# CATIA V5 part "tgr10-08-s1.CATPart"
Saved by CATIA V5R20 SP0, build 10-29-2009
Part number: TGR10-08-S1
Revision: 3
Definition: design
Nomenclature: TGR10-08-S1
Source: made
Description: NOT SPECIFIED
Bounding box of the stored display mesh (mm): x -22 to 0.8, y 0 to 10, z -5 to 5
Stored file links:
  C:\Users\Raffaele\Desktop\3D X SITO CF\I-MOLD\TGR-S1\tgr10-s1.step\tgr10-08-s1.CATPart
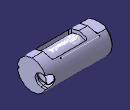
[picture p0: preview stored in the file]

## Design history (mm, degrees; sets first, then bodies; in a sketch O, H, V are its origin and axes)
Set1
  Line1 "LINE #4362": stored without definition
  DatumCurve1 "COMPOSITE_CURVE #4422"
  DatumCurve2 "COMPOSITE_CURVE #4473"
  DatumCurve3 "COMPOSITE_CURVE #4617"
  DatumCurve4 "COMPOSITE_CURVE #4696"
  DatumCurve5 "COMPOSITE_CURVE #4725"
  DatumCurve6 "COMPOSITE_CURVE #4783"
  DatumCurve7 "COMPOSITE_CURVE #4840"
  DatumCurve8 "COMPOSITE_CURVE #4883"
  DatumCurve9 "COMPOSITE_CURVE #5112"
  DatumCurve10 "COMPOSITE_CURVE #5139"
  DatumSurface1 "OPEN_SHELL #4352"
Body1 "MANIFOLD_SOLID_BREP #4353" (main body)
  Solid1: solid without history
